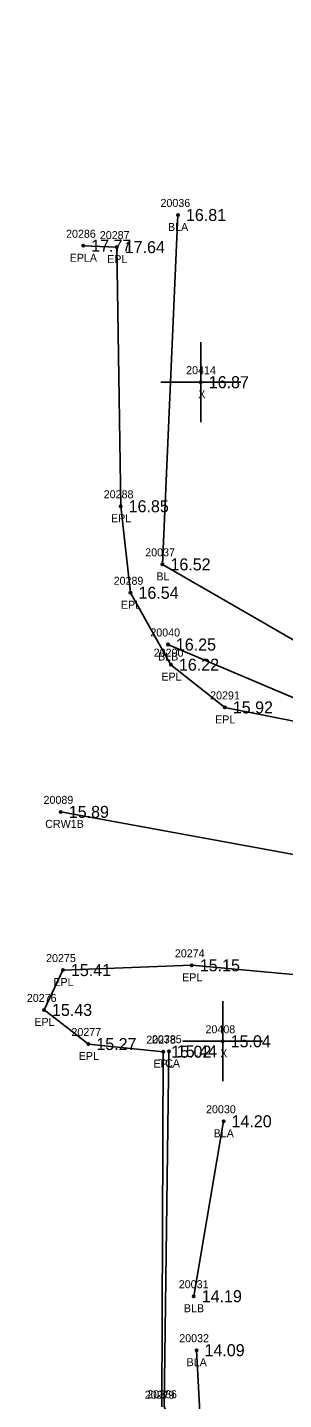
# Model space of a CAD drawing. Extents: x 2072302 to 2072980, y 127650 to 129736.
# Drawn here: x 2072727.7 to 2072759.7, y 128531.6 to 128703 of the extents above; entities that cross this region are included whole.
import ezdxf

# ---------------------------------------------------------------- set-up
doc = ezdxf.new("R2010")
doc.units = 0
for name, color, linetype in [('RD_DTM_BkLn1', 7, 'Continuous'), ('RD_DTM_BkLn2', 7, 'Continuous'), ('RD_DTM_BkLn_txCode', 7, 'Continuous'), ('RD_EX_Conc_txCode', 7, 'Continuous'), ('RD_EX_Misc', 7, 'Continuous'), ('RD_EX_Misc_txCode', 7, 'Continuous'), ('RD_EX_Road', 7, 'Continuous'), ('RD_EX_Road_txCode', 7, 'Continuous'), ('RD_EX_TX_Conc_ELEV', 7, 'Continuous'), ('RD_EX_TX_Misc_ELEV', 7, 'Continuous'), ('RD_EX_TX_Road_ELEV', 7, 'Continuous'), ('RD_HC_Survey_ELEV', 7, 'Continuous'), ('RD_HC_Survey_txCode', 7, 'Continuous'), ('RD_SMD_Locator', 7, 'Continuous')]:
    doc.layers.add(name, color=color, linetype=linetype)

msp = doc.modelspace()

# ---------------------------------------------------------------- linework, layer by layer
at = {"layer": 'RD_DTM_BkLn1'}
for p, q in [((2072752.2, 128566.35), (2072748.47, 128544.49)), ((2072748.82, 128537.75), (2072749.69, 128521.83))]:
    msp.add_line(p, q, dxfattribs=at)
for points in [[(2072746.5, 128679.57), (2072744.56, 128635.92), (2072769.36, 128621.61), (2072765.01, 128617.53), (2072745.24, 128625.91)], [(2072835.63, 128585.94), (2072819.11, 128588.9), (2072790.79, 128594.24), (2072731.84, 128605)]]:
    msp.add_lwpolyline(points, dxfattribs=at)
at = {"layer": 'RD_DTM_BkLn2'}
msp.add_lwpolyline([(2072745.36, 128575.1), (2072744.79, 128530.75), (2072749.27, 128518.05)], dxfattribs=at)
at = {"layer": 'RD_EX_Misc'}
for p, q in [((2072749.35, 128653.68), (2072749.35, 128663.68)), ((2072744.35, 128658.68), (2072754.35, 128658.68)), ((2072752.09, 128571.34), (2072752.09, 128581.34)), ((2072747.09, 128576.34), (2072757.09, 128576.34))]:
    msp.add_line(p, q, dxfattribs=at)
at = {"layer": 'RD_EX_Road'}
for points in [[(2072734.64, 128675.72), (2072738.84, 128675.55), (2072739.33, 128643.18), (2072740.56, 128632.37), (2072745.62, 128623.39), (2072752.36, 128618.05), (2072766.47, 128615.25), (2072791.47, 128612.17), (2072820.4, 128606.69), (2072833.35, 128608.3), (2072843.02, 128612.29), (2072850.8, 128617.18), (2072857.93, 128632.79), (2072859.4, 128640.06), (2072859.22, 128649.54), (2072857.79, 128659.62), (2072853.07, 128669.78), (2072812, 128703)], [(2072775.68, 128466.69), (2072812.91, 128539.86), (2072821.01, 128555.78), (2072820.61, 128560.93), (2072818.55, 128566.13), (2072816.34, 128569.6), (2072812.37, 128574.19), (2072803.55, 128578.22), (2072783.97, 128582.57), (2072748.23, 128585.83), (2072732.11, 128585.24), (2072729.74, 128580.26), (2072735.29, 128576), (2072744.65, 128575.04), (2072744.47, 128530.69)]]:
    msp.add_lwpolyline(points, dxfattribs=at)
at = {"layer": 'RD_SMD_Locator'}
for centre in [(2072746.5, 128679.57), (2072734.64, 128675.72), (2072738.84, 128675.55), (2072749.35, 128658.68), (2072739.33, 128643.18), (2072744.56, 128635.92), (2072740.56, 128632.37), (2072745.24, 128625.91), (2072745.62, 128623.39), (2072752.36, 128618.05), (2072731.84, 128605), (2072732.11, 128585.24), (2072748.23, 128585.83), (2072729.74, 128580.26), (2072735.29, 128576), (2072752.09, 128576.34), (2072744.65, 128575.04), (2072745.36, 128575.1), (2072752.2, 128566.35), (2072748.47, 128544.49), (2072748.82, 128537.75)]:
    msp.add_circle(centre, 0.15, dxfattribs=at)

# ---------------------------------------------------------------- texts
at = {"layer": 'RD_DTM_BkLn_txCode'}
for s, p in [('20036', (2072744.31, 128680.57)), ('BLA', (2072745.25, 128677.57)), ('20037', (2072742.4, 128636.92)), ('BL', (2072743.8, 128633.92)), ('20040', (2072743.04, 128626.91)), ('BLB', (2072744.01, 128623.91)), ('20030', (2072750.01, 128567.35)), ('BLA', (2072750.96, 128564.35)), ('20031', (2072746.6, 128545.49)), ('BLB', (2072747.24, 128542.49)), ('20032', (2072746.66, 128538.75)), ('BLA', (2072747.58, 128535.75))]:
    msp.add_text(s, height=1, dxfattribs=at).set_placement(p)
at = {"layer": 'RD_EX_Conc_txCode'}
for s, p in [('20385', (2072743.24, 128576.1)), ('TCA', (2072744.07, 128573.1)), ('20386', (2072742.65, 128531.75))]:
    msp.add_text(s, height=1, dxfattribs=at).set_placement(p)
at = {"layer": 'RD_EX_Misc_txCode'}
for s, p in [('20414', (2072747.52, 128659.68)), ('X', (2072749.04, 128656.68)), ('20408', (2072749.94, 128577.34)), ('X', (2072751.78, 128574.34))]:
    msp.add_text(s, height=1, dxfattribs=at).set_placement(p)
at = {"layer": 'RD_EX_Road_txCode'}
for s, p in [('20286', (2072732.5, 128676.72)), ('20287', (2072736.72, 128676.55)), ('EPLA', (2072732.95, 128673.72)), ('EPL', (2072737.64, 128673.55)), ('20288', (2072737.21, 128644.18)), ('EPL', (2072738.12, 128641.18)), ('20289', (2072738.45, 128633.37)), ('EPL', (2072739.36, 128630.37)), ('20290', (2072743.47, 128624.39)), ('EPL', (2072744.42, 128621.39)), ('20291', (2072750.52, 128619.05)), ('EPL', (2072751.15, 128616.05)), ('20275', (2072730, 128586.24)), ('20274', (2072746.11, 128586.83)), ('EPL', (2072747.02, 128583.83)), ('EPL', (2072730.91, 128583.24)), ('20276', (2072727.59, 128581.26)), ('EPL', (2072728.53, 128578.26)), ('20277', (2072733.17, 128577)), ('20278', (2072742.53, 128576.04)), ('EPL', (2072734.08, 128574)), ('EPL', (2072743.44, 128573.04)), ('20279', (2072742.35, 128531.69))]:
    msp.add_text(s, height=1, dxfattribs=at).set_placement(p)
at = {"layer": 'RD_EX_TX_Conc_ELEV'}
msp.add_text('15.44', height=1.5, dxfattribs=at).set_placement((2072746.36, 128574.35))
at = {"layer": 'RD_EX_TX_Misc_ELEV'}
for s, p in [('16.81', (2072747.5, 128678.82)), ('16.87', (2072750.35, 128657.93)), ('16.52', (2072745.56, 128635.17)), ('16.25', (2072746.24, 128625.16)), ('15.04', (2072753.09, 128575.59)), ('14.20', (2072753.2, 128565.6)), ('14.19', (2072749.47, 128543.74)), ('14.09', (2072749.82, 128537))]:
    msp.add_text(s, height=1.5, dxfattribs=at).set_placement(p)
at = {"layer": 'RD_EX_TX_Road_ELEV'}
for s, p in [('17.77', (2072735.64, 128674.97)), ('17.64', (2072739.84, 128674.8)), ('16.85', (2072740.33, 128642.43)), ('16.54', (2072741.56, 128631.62)), ('16.22', (2072746.62, 128622.64)), ('15.92', (2072753.36, 128617.3)), ('15.15', (2072749.23, 128585.08)), ('15.41', (2072733.11, 128584.49)), ('15.43', (2072730.74, 128579.51)), ('15.27', (2072736.29, 128575.25)), ('15.02', (2072745.65, 128574.29))]:
    msp.add_text(s, height=1.5, dxfattribs=at).set_placement(p)
at = {"layer": 'RD_HC_Survey_ELEV'}
msp.add_text('15.89', height=1.5, dxfattribs=at).set_placement((2072732.84, 128604.25))
at = {"layer": 'RD_HC_Survey_txCode'}
for s, p in [('20089', (2072729.68, 128606)), ('CRW1B', (2072729.89, 128603))]:
    msp.add_text(s, height=1, dxfattribs=at).set_placement(p)

doc.saveas('drawing.dxf')
